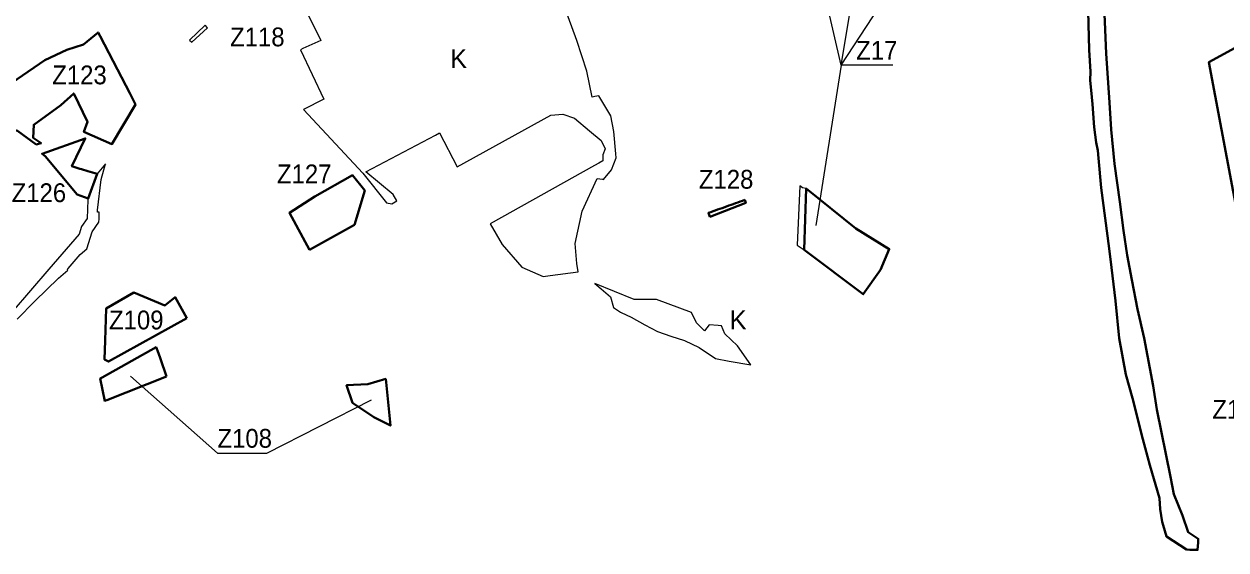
# Model space of a CAD drawing. Extents: x -650276 to -642489, y -1074311 to -1066658.
# Drawn here: x -646724 to -645192, y -1073293 to -1072621 of the extents above; entities that cross this region are included whole.
import ezdxf

# ---------------------------------------------------------------- set-up
doc = ezdxf.new("R2010")
doc.units = 0
doc.header["$LTSCALE"] = 9.6
for name, color, linetype, lineweight in [('44', 7, 'Continuous', 40), ('45', 7, 'Continuous', 40), ('46', 7, 'Continuous', 13), ('47', 7, 'Continuous', 13), ('48', 7, 'Continuous', 13), ('63', 7, 'Continuous', 13)]:
    doc.layers.add(name, color=color, linetype=linetype, lineweight=lineweight)

msp = doc.modelspace()

# ---------------------------------------------------------------- linework, layer by layer
at = {"layer": '44'}
for points in [[(-645369.364, -1072485.931), (-645372.72, -1072490.314), (-645370.928, -1072496.619), (-645370.755, -1072525.734), (-645368.173, -1072571.881), (-645366.022, -1072654.462), (-645364.524, -1072682.575), (-645364.786, -1072692.977), (-645362.708, -1072714.781)], [(-645338.023, -1072755.969), (-645339.96, -1072721.587), (-645344.152, -1072658.857), (-645347.795, -1072577.893), (-645347.214, -1072540.97), (-645348.253, -1072505.583), (-645347.292, -1072502.877)], [(-645362.708, -1072714.781), (-645361.874, -1072723.527), (-645359.76, -1072752.865), (-645357.272, -1072772.771), (-645355.121, -1072782.993)], [(-645317.65, -1072916.642), (-645322.284, -1072885.085), (-645327.091, -1072848.387), (-645333.718, -1072799.987), (-645338.023, -1072755.969)], [(-645355.121, -1072782.993), (-645354.019, -1072792.454), (-645350.822, -1072830.388), (-645340.345, -1072908.029), (-645337.34, -1072932.073), (-645332.517, -1072974.538), (-645327.554, -1073022.214), (-645319.052, -1073068.6), (-645310.558, -1073098.946), (-645297.395, -1073151.294), (-645288.647, -1073184.518), (-645276.125, -1073226.571), (-645275.269, -1073240.71), (-645272.747, -1073256.762), (-645271.518, -1073261.16)], [(-645304.24, -1072985.372), (-645311.772, -1072947.945), (-645317.65, -1072916.642)], [(-645257.842, -1073221.36), (-645262.388, -1073199.409), (-645279.878, -1073113.356), (-645284.269, -1073083.286), (-645295.788, -1073022.556), (-645304.24, -1072985.372)], [(-645237.524, -1073292.361), (-645227.744, -1073292.735), (-645227.199, -1073283.366), (-645226.847, -1073278.345), (-645239.9, -1073270.025), (-645247.051, -1073248.736), (-645257.842, -1073221.36)], [(-645271.518, -1073261.16), (-645267.525, -1073275.443), (-645241.72, -1073292.2), (-645237.524, -1073292.361)]]:
    msp.add_lwpolyline(points, dxfattribs=at)
at = {"layer": '45'}
for points in [[(-646737.05, -1072756.4), (-646732.5, -1072757.63), (-646708.65, -1072775.02), (-646702.45, -1072773.39), (-646712.46, -1072766.76), (-646711.79, -1072750.02), (-646677.39, -1072724.85), (-646660.89, -1072709.97), (-646643.36, -1072746.04), (-646647.93, -1072759.01), (-646612.11, -1072774.56), (-646581.92, -1072723.91), (-646589.37, -1072709.83), (-646605.23, -1072679.37), (-646627.32, -1072636.95), (-646629.86, -1072632.07), (-646648.27, -1072647.48), (-646669.6, -1072654.53), (-646697.89, -1072667.65)], [(-645180.05, -1072651.77), (-645213.34, -1072669.98), (-645174.13, -1072877.93)], [(-646697.89, -1072667.65), (-646732.95, -1072691.68), (-646759.491, -1072709.878), (-646757.5, -1072713.3), (-646747.87, -1072729.85), (-646744.94, -1072734.88), (-646748.3, -1072737.01), (-646737.05, -1072756.4)], [(-646653.02, -1072806.07), (-646663.07, -1072803.04), (-646663.07, -1072803.04), (-646646.12, -1072767.32), (-646646.31, -1072767.388), (-646701.12, -1072787.08), (-646697.09, -1072790.03), (-646656.36, -1072839.08)], [(-646656.36, -1072839.08), (-646642.404, -1072844.195), (-646631.08, -1072812.68), (-646643.01, -1072809.08), (-646651.11, -1072806.64), (-646653.02, -1072806.07)], [(-645849.703, -1072867.622), (-645848.52, -1072867.16), (-645803.84, -1072849.72), (-645805.159, -1072845.994)], [(-645805.159, -1072845.994), (-645808.177, -1072847.063), (-645811.148, -1072848.124), (-645813.978, -1072849.124), (-645816.948, -1072850.184), (-645819.779, -1072851.184), (-645822.726, -1072852.233), (-645825.527, -1072853.233), (-645828.409, -1072854.254), (-645834.208, -1072856.314)], [(-645834.208, -1072856.314), (-645837.027, -1072857.313), (-645839.908, -1072858.343), (-645842.74, -1072859.344), (-645845.619, -1072860.364), (-645848.628, -1072861.433), (-645851.48, -1072862.586), (-645850.187, -1072866.251), (-645850.17, -1072866.3), (-645849.705, -1072867.618), (-645849.703, -1072867.622)], [(-646542.62, -1073071.1), (-646550.01, -1073048.55), (-646552.79, -1073041.53), (-646555.79, -1073033.92), (-646624.69, -1073072.66), (-646626.967, -1073073.918), (-646621.38, -1073102.66)], [(-646542.62, -1073071.1), (-646550.01, -1073048.55), (-646552.79, -1073041.53), (-646555.79, -1073033.92), (-646624.69, -1073072.66), (-646626.967, -1073073.918), (-646621.38, -1073102.66)], [(-646542.62, -1073071.1), (-646550.01, -1073048.55), (-646552.79, -1073041.53), (-646555.79, -1073033.92), (-646624.69, -1073072.66), (-646626.967, -1073073.918), (-646621.38, -1073102.66)], [(-646542.62, -1073071.1), (-646550.01, -1073048.55), (-646552.79, -1073041.53), (-646555.79, -1073033.92), (-646624.69, -1073072.66), (-646626.967, -1073073.918), (-646621.38, -1073102.66)], [(-646621.38, -1073102.66), (-646620.19, -1073102.14), (-646618.56, -1073101.42), (-646542.62, -1073071.1)], [(-646621.38, -1073102.66), (-646620.19, -1073102.14), (-646618.56, -1073101.42), (-646542.62, -1073071.1)], [(-646621.38, -1073102.66), (-646620.19, -1073102.14), (-646618.56, -1073101.42), (-646542.62, -1073071.1)], [(-646621.38, -1073102.66), (-646620.19, -1073102.14), (-646618.56, -1073101.42), (-646542.62, -1073071.1)], [(-646262.94, -1073074.15), (-646285.77, -1073081.01), (-646312.87, -1073082.4), (-646305.18, -1073104.8), (-646278.38, -1073123.25)], [(-646262.94, -1073074.15), (-646285.77, -1073081.01), (-646312.87, -1073082.4), (-646305.18, -1073104.8), (-646278.38, -1073123.25)], [(-646278.38, -1073123.25), (-646257.09, -1073134.01), (-646262.94, -1073074.15)], [(-646278.38, -1073123.25), (-646257.09, -1073134.01), (-646262.94, -1073074.15)]]:
    msp.add_lwpolyline(points, dxfattribs=at)
for points in [[(-646360.22, -1072909.57), (-646303.02, -1072877.74), (-646289.63, -1072834.04), (-646305.56, -1072814.43), (-646353.25, -1072841.63), (-646385.86, -1072862.59)], [(-645729.36, -1072909.65), (-645654.16, -1072966.3), (-645632.23, -1072935.28), (-645620.92, -1072908.65), (-645663.52, -1072882.58), (-645726.9, -1072831.5)], [(-645729.36, -1072909.65), (-645654.16, -1072966.3), (-645632.23, -1072935.28), (-645620.92, -1072908.65), (-645663.52, -1072882.58), (-645726.9, -1072831.5)], [(-646516.7, -1072996.65), (-646531.46, -1072970.12), (-646544.68, -1072980.62), (-646584.23, -1072964.22), (-646619.48, -1072984.34), (-646620.71, -1073025.49), (-646621.44, -1073049.79), (-646616.55, -1073052.21)], [(-646516.7, -1072996.65), (-646531.46, -1072970.12), (-646544.68, -1072980.62), (-646584.23, -1072964.22), (-646619.48, -1072984.34), (-646620.71, -1073025.49), (-646621.44, -1073049.79), (-646616.55, -1073052.21)]]:
    msp.add_lwpolyline(points, close=True, dxfattribs=at)
at = {"layer": '46'}
for p, q in [((-645682.434, -1072673.943), (-645625.498, -1072333.934)), ((-645682.434, -1072673.943), (-645729.938, -1072467.657)), ((-645682.434, -1072673.943), (-645729.938, -1072467.657)), ((-645682.434, -1072673.943), (-645581.338, -1072519.311)), ((-645682.434, -1072673.943), (-645714.669, -1072878.528)), ((-645682.434, -1072673.943), (-645714.669, -1072878.528)), ((-645616.267, -1072673.943), (-645682.434, -1072673.943))]:
    msp.add_line(p, q, dxfattribs=at)
msp.add_lwpolyline([(-646588.523, -1073070.963), (-646477.555, -1073169.273), (-646414.561, -1073169.273), (-646281.126, -1073101.085)], dxfattribs=at)
msp.add_lwpolyline([(-646588.523, -1073070.963), (-646477.555, -1073169.273), (-646414.561, -1073169.273), (-646281.126, -1073101.085)], dxfattribs=at)
at = {"layer": '47'}
msp.add_line((-645882.07, -1073025.22), (-645863.39, -1073034.25), dxfattribs=at)
for points in [[(-645999.622, -1072714.927), (-646006.66, -1072681.4), (-646019.16, -1072642.35), (-646030.17, -1072612.31), (-646043.87, -1072578.12), (-646056.42, -1072556.49), (-646075.82, -1072525.54), (-646110.61, -1072477.49), (-646153.49, -1072431.54), (-646172.81, -1072418.2), (-646184.449, -1072410.256), (-646194.19, -1072404.62), (-646254.75, -1072404.25), (-646243.17, -1072432.88), (-646282.47, -1072474.34), (-646328.45, -1072504.81), (-646315.452, -1072531.573)], [(-646315.452, -1072531.573), (-646320.62, -1072534.6), (-646350.18, -1072550.59), (-646382.41, -1072568.01), (-646345.6, -1072642.55), (-646368.51, -1072652.81), (-646371.66, -1072654.2), (-646342.08, -1072717.43), (-646367.72, -1072730.68), (-646321.171, -1072780.535), (-646292.17, -1072811.6), (-646261.97, -1072849.66), (-646255.39, -1072850.83), (-646249.04, -1072847.16), (-646253.56, -1072838.8), (-646288.27, -1072810.22), (-646199.72, -1072763.1), (-646194.296, -1072760.193)], [(-645969.46, -1072787.03), (-645972.31, -1072758.48), (-645975.86, -1072738.61), (-645991.31, -1072712.86), (-645996.31, -1072714.11), (-645999.622, -1072714.927)], [(-646194.296, -1072760.193), (-646171.72, -1072803.51), (-646052.58, -1072737.82), (-646037.23, -1072736.38), (-646022.4, -1072741.58), (-646003.22, -1072757.85), (-645988.43, -1072769.93), (-645983.22, -1072780.88), (-645986.24, -1072788.33), (-645986.359, -1072796.127)], [(-645975.3, -1072807.37), (-645969.01, -1072792.28), (-645969.46, -1072787.03)], [(-646732.95, -1072998.07), (-646710.3, -1072975.31), (-646680.07, -1072945.74), (-646668.53, -1072935.52), (-646669.198, -1072934.569), (-646668.09, -1072933.43), (-646652.76, -1072915.66), (-646644.069, -1072908.218), (-646644.061, -1072908.209), (-646644.059, -1072908.208), (-646637.2, -1072886.57), (-646628.7, -1072874.5), (-646628.58, -1072869.88), (-646628.36, -1072861.71), (-646630.76, -1072861.61), (-646630.57, -1072859.99), (-646630.45, -1072858.93), (-646625.91, -1072819.66), (-646620.27, -1072799.95), (-646631.08, -1072812.68), (-646640.313, -1072838.394), (-646642.404, -1072844.195), (-646642.39, -1072844.2), (-646642.438, -1072844.29), (-646642.939, -1072845.68), (-646643.574, -1072869.57), (-646650.798, -1072879.828), (-646653.846, -1072889.44), (-646692.432, -1072934.135), (-646739.241, -1072988.798)], [(-645986.359, -1072796.127), (-645991.37, -1072798.84), (-645996.8, -1072801.88), (-646129.91, -1072876.24), (-646114.5, -1072902.8), (-646089.39, -1072931.92), (-646062.04, -1072943.58), (-646053.287, -1072942.399), (-646017.65, -1072937.59), (-646019.21, -1072926.91), (-646021.64, -1072901.6), (-646012.37, -1072860.3), (-645993.47, -1072818.44), (-645986.71, -1072819.26), (-645985.19, -1072819.72), (-645975.3, -1072807.37)], [(-645866.93, -1073002.72), (-645873.3, -1072989.79), (-645917.53, -1072972.93), (-645946.4, -1072973.05), (-645996.2, -1072952.69)], [(-645996.2, -1072952.69), (-645988.49, -1072959.28), (-645976.48, -1072969.55), (-645972.6, -1072983.41)], [(-645972.6, -1072983.41), (-645963.77, -1072989), (-645962.81, -1072989.45), (-645949.85, -1072995.57), (-645932.44, -1073005.5), (-645916.47, -1073014.03), (-645899.35, -1073019.65), (-645882.07, -1073025.22)], [(-645838.89, -1073006.18), (-645850.37, -1073005.42), (-645856.46, -1073013.07), (-645858.82, -1073010.74), (-645866.93, -1073002.72)], [(-645830.6, -1073016.92), (-645834.9, -1073006.45), (-645838.89, -1073006.18)], [(-645863.39, -1073034.25), (-645842.53, -1073048.19), (-645824.93, -1073051.83), (-645797.32, -1073056.62), (-645814.27, -1073032.11), (-645830.6, -1073016.92)]]:
    msp.add_lwpolyline(points, dxfattribs=at)
msp.add_lwpolyline([(-646493.229, -1072622.74), (-646513.209, -1072641.935), (-646510.28, -1072644.42), (-646490.11, -1072626.15)], close=True, dxfattribs=at)
at = {"layer": '63'}
msp.add_line((-646621.38, -1073102.66), (-646542.62, -1073071.1), dxfattribs=at)
for points in [[(-645176.757, -1072649.968), (-645213.34, -1072669.98), (-645185.613, -1072817.031), (-645185.613, -1072817.031)], [(-645735.02, -1072827.73), (-645738.444, -1072903.485), (-645729.36, -1072909.65), (-645654.16, -1072966.3)], [(-645663.52, -1072882.58), (-645726.9, -1072831.5), (-645731.6, -1072830.54), (-645735.02, -1072827.73)], [(-645654.16, -1072966.3), (-645632.23, -1072935.28), (-645620.92, -1072908.65), (-645663.52, -1072882.58)], [(-646516.7, -1072996.65), (-646531.46, -1072970.12), (-646544.68, -1072980.62), (-646584.23, -1072964.22), (-646619.48, -1072984.34), (-646621.44, -1073049.79)], [(-646621.44, -1073049.79), (-646616.55, -1073052.21), (-646516.7, -1072996.65)], [(-646555.79, -1073033.92), (-646627, -1073073.75), (-646621.38, -1073102.66)], [(-646542.62, -1073071.1), (-646550.01, -1073048.55), (-646555.79, -1073033.92)], [(-646262.94, -1073074.15), (-646285.77, -1073081.01), (-646312.87, -1073082.4)], [(-646312.87, -1073082.4), (-646305.18, -1073104.8), (-646305.18, -1073104.8)], [(-646305.18, -1073104.8), (-646278.38, -1073123.25), (-646257.09, -1073134.01), (-646262.94, -1073074.15)]]:
    msp.add_lwpolyline(points, dxfattribs=at)

# ---------------------------------------------------------------- texts
at = {"layer": '46', "width": 0.95}
for s, p in [('Z118', (-646461.466, -1072649.857)), ('Z17', (-645663.172, -1072666.966)), ('Z123', (-646688.261, -1072698.34)), ('Z127', (-646401.702, -1072824.699)), ('Z128', (-645863.685, -1072831.559)), ('Z126', (-646740.041, -1072848.718)), ('Z109', (-646615.842, -1073011.142)), ('Z109', (-646615.842, -1073011.142)), ('Z115', (-645208.897, -1073125.218)), ('Z108', (-646477.565, -1073162.229)), ('Z108', (-646477.565, -1073162.229))]:
    msp.add_text(s, height=24, dxfattribs=at).set_placement(p)
at = {"layer": '48'}
for p in [(-646180.786, -1072677.559), (-646180.786, -1072677.559), (-645824.362, -1073011.011), (-645824.362, -1073011.011)]:
    msp.add_text('K', height=24, dxfattribs=at).set_placement(p)

doc.saveas('drawing.dxf')
